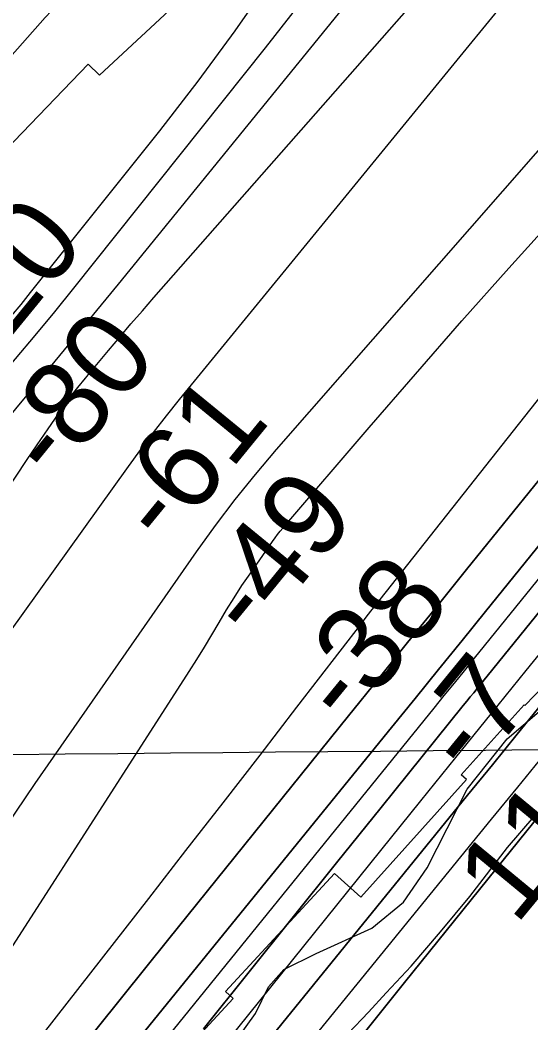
# Model space of a CAD drawing. Extents: x 3598634 to 3636690, y 517270 to 542944.
# Drawn here: x 3607463 to 3607864, y 528569 to 529355 of the extents above; entities that cross this region are included whole.
import ezdxf

# ---------------------------------------------------------------- set-up
doc = ezdxf.new("R2010")
doc.units = 0
for name, color, linetype in [('V-GRID-MAJR', 7, 'Continuous'), ('V-RIVR-EDGE', 7, 'Continuous'), ('V-RIVR-RANG', 7, 'Continuous'), ('V-RRAP-RVMT', 7, 'Continuous'), ('V-SITE-VEGE', 7, 'Continuous'), ('V-TOPO-DPTH', 7, 'Continuous'), ('V-TOPO-MAJR', 7, 'Continuous'), ('V-TOPO-MINR', 7, 'Continuous'), ('V-TOPO-WATR', 7, 'Continuous')]:
    doc.layers.add(name, color=color, linetype=linetype)

msp = doc.modelspace()

# ---------------------------------------------------------------- linework, layer by layer
at = {"layer": 'V-GRID-MAJR'}
msp.add_spline([(3602797.865, 528737.682), (3608075.829, 528784.895), (3613353.788, 528832.875), (3618631.739, 528881.623), (3623909.683, 528931.139), (3629187.62, 528981.4230000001), (3634465.549, 529032.474), (3634465.5500000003, 529032.474)], degree=3, dxfattribs=at)
at = {"layer": 'V-RIVR-EDGE'}
msp.add_lwpolyline([(3607634.578266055, 528557.2828526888), (3607647.8313884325, 528575.8602071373), (3607658.088833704, 528596.8462755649), (3607670.1294347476, 528610.6240151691), (3607695.3741721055, 528623.1684514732), (3607739.246734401, 528642.8707461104), (3607763.9104463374, 528663.220865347), (3607782.5872573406, 528690.1893814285), (3607813.9569472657, 528751.9454563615), (3607845.2717134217, 528791.489581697), (3607870.5387171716, 528813.0388624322), (3607896.9930070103, 528829.1822676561)], dxfattribs=at)
at = {"layer": 'V-RRAP-RVMT'}
for p, q in [((3607594.1901712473, 529376.2780618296), (3607525.4960925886, 529312.2596277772)), ((3607516.580398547, 529320.8680197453), (3607430.4427041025, 529231.6699390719)), ((3607525.4960925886, 529312.2596277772), (3607516.580398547, 529320.8680197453)), ((3607859.168962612, 528817.6532788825), (3607945.306657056, 528906.851359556)), ((3607809.3275471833, 528763.2942775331), (3607858.69286742, 528818.1145164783)), ((3607858.69286742, 528818.1145164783), (3607859.168962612, 528817.6532788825)), ((3607813.5323175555, 528759.4914313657), (3607809.3275471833, 528763.2942775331)), ((3607730.560063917, 528667.341525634), (3607813.5323175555, 528759.4914313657)), ((3607624.2160000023, 528593.327), (3607709.927226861, 528685.9194392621)), ((3607709.927226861, 528685.9194392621), (3607730.560063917, 528667.341525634)), ((3607529.4030000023, 528478.7670000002), (3607630.2730000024, 528587.7050000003)), ((3607630.2730000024, 528587.7050000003), (3607624.2160000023, 528593.327))]:
    msp.add_line(p, q, dxfattribs=at)
at = {"layer": 'V-SITE-VEGE'}
for points in [[(3607770.066, 528613.019), (3607793.127, 528640.116), (3607816.1890000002, 528667.909), (3607845.549, 528706.131), (3607866.5130000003, 528730.447)], [(3607720.468, 528560.229), (3607736.532, 528576.898), (3607750.506, 528592.18), (3607770.066, 528613.019)]]:
    msp.add_lwpolyline(points, dxfattribs=at)
at = {"layer": 'V-TOPO-DPTH'}
for points in [[(3607050.110421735, 527933.8661143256), (3607754.6678173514, 528800.4477853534), (3607773.1231306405, 528823.1621606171), (3607791.5686676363, 528845.8844668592), (3607809.999540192, 528868.6186695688), (3607828.420636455, 528891.360803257), (3608108.5226418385, 529237.3945285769), (3608193.270411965, 529341.3823736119), (3608278.475807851, 529444.99132357), (3608364.367642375, 529548.0319309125), (3608450.7171026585, 529650.6936431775), (3608605.4413867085, 529833.411271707), (3608614.8399220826, 529844.369931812), (3608624.329041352, 529855.2485710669), (3608633.9540364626, 529866.0071790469), (3608643.669615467, 529876.6857661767), (3609104.282173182, 530376.6107843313)], [(3609104.282173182, 530376.6107843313), (3608643.669615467, 529876.6857661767), (3608633.9540364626, 529866.0071790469), (3608624.329041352, 529855.2485710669), (3608614.8399220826, 529844.369931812), (3608605.4413867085, 529833.411271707), (3608450.7171026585, 529650.6936431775), (3608364.367642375, 529548.0319309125), (3608278.475807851, 529444.99132357), (3608193.270411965, 529341.3823736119), (3608108.5226418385, 529237.3945285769), (3607828.420636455, 528891.360803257), (3607809.999540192, 528868.6186695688), (3607791.5686676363, 528845.8844668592), (3607773.1231306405, 528823.1621606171), (3607754.6678173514, 528800.4477853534), (3607050.110421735, 527933.8661143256)], [(3608991.262616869, 530147.8676727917), (3608718.8075875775, 529843.8314700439), (3608702.0593536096, 529824.9491268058), (3608685.4407747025, 529805.9545085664), (3608669.0166783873, 529786.7914778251), (3608652.722237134, 529767.5161720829), (3608514.674114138, 529602.5153722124), (3608429.6663916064, 529500.4793089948), (3608344.943345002, 529398.2084138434), (3608260.647312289, 529295.5852707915), (3608176.635955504, 529192.7272958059), (3607892.148238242, 528842.9338263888), (3607872.700147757, 528819.0185201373), (3607853.2538833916, 528795.1017292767), (3607833.8103582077, 528771.182711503), (3607814.3686591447, 528747.262209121), (3607476.376953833, 528331.3583664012)], [(3607476.376953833, 528331.3583664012), (3607814.3686591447, 528747.262209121), (3607833.8103582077, 528771.182711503), (3607853.2538833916, 528795.1017292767), (3607872.700147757, 528819.0185201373), (3607892.148238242, 528842.9338263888), (3608176.635955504, 529192.7272958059), (3608260.647312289, 529295.5852707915), (3608344.943345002, 529398.2084138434), (3608429.6663916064, 529500.4793089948), (3608514.674114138, 529602.5153722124), (3608652.722237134, 529767.5161720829), (3608669.0166783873, 529786.7914778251), (3608685.4407747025, 529805.9545085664), (3608702.0593536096, 529824.9491268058), (3608718.8075875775, 529843.8314700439), (3608991.262616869, 530147.8676727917)], [(3607034.223612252, 527987.6309703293), (3607564.046678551, 528666.2927235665), (3607593.2248466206, 528703.7456360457), (3607622.3524560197, 528741.2377456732), (3607651.404227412, 528778.788651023), (3607680.405440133, 528816.378753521), (3607731.2039673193, 528882.3593449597), (3607734.7769871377, 528886.9815347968), (3607738.3619932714, 528891.5943715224), (3607741.9649788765, 528896.1931785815), (3607745.5799507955, 528900.7826325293), (3608274.0892009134, 529569.0736764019), (3608320.3402500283, 529626.5951807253), (3608367.2018034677, 529683.6065428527), (3608414.9791133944, 529739.8526916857), (3608463.3669276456, 529795.5886983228), (3608554.5295855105, 529898.8959307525)], [(3607034.223612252, 527987.6309703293), (3607564.046678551, 528666.2927235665), (3607593.2248466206, 528703.7456360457), (3607622.3524560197, 528741.2377456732), (3607651.404227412, 528778.788651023), (3607680.405440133, 528816.378753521), (3607731.2039673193, 528882.3593449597), (3607734.7769871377, 528886.9815347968), (3607738.3619932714, 528891.5943715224), (3607741.9649788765, 528896.1931785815), (3607745.5799507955, 528900.7826325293), (3608274.0892009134, 529569.0736764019), (3608320.3402500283, 529626.5951807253), (3608367.2018034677, 529683.6065428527), (3608414.9791133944, 529739.8526916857), (3608463.3669276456, 529795.5886983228), (3608554.5295855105, 529898.8959307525)], [(3607486.2819548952, 528518.1246214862), (3607579.8394687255, 528634.4834955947), (3607720.9145705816, 528809.5522122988), (3607744.066510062, 528838.2711207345), (3607767.226098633, 528866.9838569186), (3607790.397160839, 528895.6873347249), (3607813.5758721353, 528924.3846402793), (3607874.8316391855, 529000.1937296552), (3607928.7530441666, 529066.7018234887), (3607982.8198766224, 529133.0910840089), (3608037.1048502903, 529199.302094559), (3608091.535251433, 529265.3942717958), (3608556.611860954, 529828.2246806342), (3608577.032808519, 529852.5722801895), (3608597.6881704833, 529876.7163432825), (3608618.6951540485, 529900.5551016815)], [(3608618.6951540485, 529900.5551016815), (3608597.6881704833, 529876.7163432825), (3608577.032808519, 529852.5722801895), (3608556.611860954, 529828.2246806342), (3608091.535251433, 529265.3942717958), (3608037.1048502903, 529199.302094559), (3607982.8198766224, 529133.0910840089), (3607928.7530441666, 529066.7018234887), (3607874.8316391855, 529000.1937296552), (3607813.5758721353, 528924.3846402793), (3607790.397160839, 528895.6873347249), (3607767.226098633, 528866.9838569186), (3607744.066510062, 528838.2711207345), (3607720.9145705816, 528809.5522122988), (3607579.8394687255, 528634.4834955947), (3607486.2819548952, 528518.1246214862)], [(3608692.0499146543, 529894.310394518), (3608646.0571142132, 529844.3928552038), (3608644.3113008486, 529842.4744016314), (3608642.5815031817, 529840.5417904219), (3608640.875729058, 529838.5879427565), (3608639.1859706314, 529836.6199374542), (3608610.975637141, 529803.3503869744), (3608595.2558213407, 529784.6846881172), (3608579.620121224, 529765.9492680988), (3608564.110594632, 529747.1092663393), (3608548.685183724, 529728.1995434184), (3607821.8677533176, 528831.0740898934), (3607819.144475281, 528827.7105861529), (3607816.4225722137, 528824.3459707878), (3607813.7027316, 528820.9796879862), (3607810.984265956, 528817.61229356), (3607746.463470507, 528737.6395229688), (3607711.520787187, 528694.2567081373), (3607676.6249686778, 528650.8362916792), (3607641.799447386, 528607.3594727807), (3607607.020790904, 528563.8450522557)], [(3607607.020790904, 528563.8450522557), (3607641.799447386, 528607.3594727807), (3607676.6249686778, 528650.8362916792), (3607711.520787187, 528694.2567081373), (3607746.463470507, 528737.6395229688), (3607810.984265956, 528817.61229356), (3607813.7027316, 528820.9796879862), (3607816.4225722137, 528824.3459707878), (3607819.144475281, 528827.7105861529), (3607821.8677533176, 528831.0740898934), (3608548.685183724, 529728.1995434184), (3608564.110594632, 529747.1092663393), (3608579.620121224, 529765.9492680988), (3608595.2558213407, 529784.6846881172), (3608610.975637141, 529803.3503869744), (3608639.1859706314, 529836.6199374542), (3608640.875729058, 529838.5879427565), (3608642.5815031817, 529840.5417904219), (3608644.3113008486, 529842.4744016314), (3608646.0571142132, 529844.3928552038), (3608692.0499146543, 529894.310394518)], [(3608826.278553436, 529889.7496636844), (3608805.0948457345, 529867.4214339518), (3608784.247844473, 529844.7785133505), (3608763.6253141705, 529821.9257988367), (3608724.162120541, 529777.5310744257), (3608723.444853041, 529776.7138432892), (3608722.7345501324, 529775.8906787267), (3608721.3418026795, 529774.2206158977), (3607992.342167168, 528881.1336073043), (3607976.182451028, 528861.3303280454), (3607960.0268139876, 528841.5237226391), (3607943.8772955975, 528821.7121280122), (3607927.731856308, 528801.8972072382), (3607900.6113318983, 528768.6023214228), (3607898.0316686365, 528765.4303601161), (3607895.455278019, 528762.2557470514), (3607892.88379637, 528759.0771563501), (3607890.315587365, 528755.8959138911), (3607830.1698473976, 528681.2754461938), (3607797.532199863, 528640.781193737), (3607764.895854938, 528600.2858915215), (3607732.261463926, 528559.7890146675)]]:
    msp.add_lwpolyline(points, dxfattribs=at)
at = {"layer": 'V-TOPO-MAJR'}
for points in [[(3606938.5062461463, 528528.361308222), (3607012.804781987, 528597.746612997), (3607085.3402082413, 528668.8656599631), (3607155.2309701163, 528742.5853202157), (3607223.3586224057, 528818.0387226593), (3607443.875212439, 529071.4225473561), (3607459.518815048, 529089.6314336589), (3607475.005335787, 529107.9712529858), (3607490.256233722, 529126.507471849), (3607505.3500497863, 529145.1746237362), (3607655.732426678, 529333.6088707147), (3607744.7138808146, 529447.4732628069), (3607832.115936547, 529562.5123585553), (3607917.1488946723, 529679.3135097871), (3608000.6024543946, 529797.2893646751), (3608165.5331937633, 530035.5755289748)], [(3607396.4622327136, 528534.538567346), (3607595.724040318, 528844.2248021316), (3607601.7802237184, 528853.7867448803), (3607607.7442807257, 528863.4049053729), (3607613.57014814, 528873.1073924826), (3607619.3038891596, 528882.8660973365), (3607625.089083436, 528892.590358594), (3607631.034815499, 528902.2126010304), (3607637.221354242, 528911.6818152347), (3607643.568430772, 528921.0490106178), (3607661.255984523, 528946.4565765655), (3607663.1754045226, 528949.1261234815), (3607665.147564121, 528951.7548337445), (3607667.1988331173, 528954.3222890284), (3607669.3028417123, 528956.8489076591), (3607737.1862056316, 529035.8879061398), (3607773.4384315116, 529077.7560607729), (3607809.9131516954, 529119.4278847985), (3607846.721613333, 529160.8052129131), (3607883.752569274, 529201.9862104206), (3608512.639176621, 529895.7241702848)]]:
    msp.add_lwpolyline(points, dxfattribs=at)
at = {"layer": 'V-TOPO-MINR'}
for points in [[(3607269.9346052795, 528037.4466619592), (3607833.1789492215, 528728.441475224), (3607853.695733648, 528753.6155649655), (3607874.209999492, 528778.7917066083), (3607894.720487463, 528803.9709261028), (3607915.2284568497, 528829.1521974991), (3608012.971921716, 528949.1875763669), (3608082.5213329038, 529034.2464083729), (3608152.2995331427, 529119.1163572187), (3608222.420916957, 529203.7029813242), (3608292.771089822, 529288.1007222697), (3608697.7320062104, 529771.9288514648), (3608703.7902030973, 529779.1057189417), (3608709.8880741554, 529786.2484280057), (3608716.04545647, 529793.3398994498), (3608722.2425129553, 529800.3972124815), (3609349.791717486, 530509.062902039)], [(3607050.110421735, 527933.8661143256), (3607754.6678173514, 528800.4477853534), (3607773.1231306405, 528823.1621606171), (3607791.5686676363, 528845.8844668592), (3607809.999540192, 528868.6186695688), (3607828.420636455, 528891.360803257), (3608108.5226418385, 529237.3945285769), (3608193.270411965, 529341.3823736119), (3608278.475807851, 529444.99132357), (3608364.367642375, 529548.0319309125), (3608450.7171026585, 529650.6936431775), (3608605.4413867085, 529833.411271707), (3608614.8399220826, 529844.369931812), (3608624.329041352, 529855.2485710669), (3608633.9540364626, 529866.0071790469), (3608643.669615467, 529876.6857661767), (3609104.282173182, 530376.6107843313)], [(3607153.579419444, 528530.0961648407), (3607214.1284992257, 528623.3245871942), (3607451.633225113, 528985.0946669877), (3607459.8764041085, 528997.5484505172), (3607468.1816531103, 529009.9603620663), (3607476.58000712, 529022.3094656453), (3607485.0404311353, 529034.616697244), (3607496.207898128, 529050.7316771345), (3607499.1759406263, 529054.9164984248), (3607502.2036420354, 529059.0566857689), (3607505.32083181, 529063.1299221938), (3607508.497680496, 529067.1585246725), (3607514.438003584, 529074.5249937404), (3607514.690223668, 529074.8362432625), (3607515.4537861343, 529075.7643346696), (3607532.4574206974, 529096.1767786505), (3607541.2583585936, 529106.6542355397), (3607550.1162340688, 529117.0829268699), (3607559.059515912, 529127.438469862), (3607568.059735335, 529137.7452472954), (3608344.7420183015, 530019.8355773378)], [(3607538.861497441, 528507.8470592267), (3607788.102173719, 528815.6048933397), (3607796.0217690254, 528825.383855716), (3607803.941370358, 528835.1628132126), (3607811.8609807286, 528844.9417633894), (3607819.7805971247, 528854.7207086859), (3608327.2406076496, 529481.3191128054), (3608377.5500924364, 529543.0180431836), (3608428.1322050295, 529604.4911170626), (3608479.123259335, 529665.6254061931), (3608530.386941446, 529726.5338388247), (3608622.313038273, 529835.0183809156), (3608627.857922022, 529841.4799990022), (3608633.4557975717, 529847.8947890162), (3608639.1331608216, 529854.2393369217), (3608644.863515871, 529860.5370567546), (3608795.867747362, 530024.4293374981)], [(3607315.303971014, 528512.7430944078), (3607366.934778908, 528595.0148138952), (3607420.365062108, 528676.1294302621), (3607474.994995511, 528756.4726445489), (3607601.505611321, 528938.1919034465), (3607616.4214247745, 528958.8716412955), (3607631.783973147, 528979.2019377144), (3607647.8166238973, 528999.0080719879), (3607664.2960095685, 529018.4647648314), (3608476.761360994, 529945.8585601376)], [(3608167.609300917, 529919.3445388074), (3608117.7852957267, 529858.0963726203), (3608067.950229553, 529796.8572059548), (3608018.10778939, 529735.62403897), (3607539.9595716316, 529148.3106995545), (3607517.056991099, 529120.2706469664), (3607494.0950201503, 529092.2794725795), (3607471.0439635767, 529064.3616154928), (3607447.9335165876, 529036.4926366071), (3606763.4822901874, 528213.7816602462), (3606757.299481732, 528206.281166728), (3606751.1622999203, 528198.743864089), (3606745.0935580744, 528191.1513477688), (3606739.070442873, 528183.5220223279), (3606733.287483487, 528175.730280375), (3606727.7774810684, 528167.7598566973), (3606722.6769141, 528159.5214104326), (3606717.8493040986, 528151.1042824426), (3606633.923438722, 527995.8083232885), (3606585.2959337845, 527910.9416458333), (3606533.960073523, 527827.8424987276), (3606478.5616802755, 527747.3946471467), (3606420.4549317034, 527668.7143259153), (3606248.639550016, 527447.7750288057)], [(3607034.223612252, 527987.6309703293), (3607564.046678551, 528666.2927235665), (3607593.2248466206, 528703.7456360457), (3607622.3524560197, 528741.2377456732), (3607651.404227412, 528778.788651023), (3607680.405440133, 528816.378753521), (3607731.2039673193, 528882.3593449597), (3607734.7769871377, 528886.9815347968), (3607738.3619932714, 528891.5943715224), (3607741.9649788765, 528896.1931785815), (3607745.5799507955, 528900.7826325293), (3608274.0892009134, 529569.0736764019), (3608320.3402500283, 529626.5951807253), (3608367.2018034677, 529683.6065428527), (3608414.9791133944, 529739.8526916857), (3608463.3669276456, 529795.5886983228), (3608554.5295855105, 529898.8959307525)], [(3607230.391889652, 528518.152562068), (3607261.079917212, 528571.3685838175), (3607291.875722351, 528624.5226713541), (3607297.412073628, 528634.04516238), (3607331.865051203, 528691.3908644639), (3607367.3935200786, 528748.0403263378), (3607404.5352259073, 528803.6454278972), (3607442.7524230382, 528858.554289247), (3607548.0453323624, 529005.2903303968), (3607557.7997309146, 529018.6145053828), (3607567.720346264, 529031.8112339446), (3607577.890286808, 529044.816792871), (3607588.2264441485, 529057.6949053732), (3608053.775307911, 529626.5599169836), (3608110.773650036, 529695.4553882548), (3608168.256237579, 529763.9399911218), (3608226.4651932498, 529831.8082913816), (3608285.1583943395, 529899.2657232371)], [(3607486.2819548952, 528518.1246214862), (3607579.8394687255, 528634.4834955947), (3607720.9145705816, 528809.5522122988), (3607744.066510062, 528838.2711207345), (3607767.226098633, 528866.9838569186), (3607790.397160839, 528895.6873347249), (3607813.5758721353, 528924.3846402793), (3607874.8316391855, 529000.1937296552), (3607928.7530441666, 529066.7018234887), (3607982.8198766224, 529133.0910840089), (3608037.1048502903, 529199.302094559), (3608091.535251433, 529265.3942717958), (3608556.611860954, 529828.2246806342), (3608577.032808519, 529852.5722801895), (3608597.6881704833, 529876.7163432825), (3608618.6951540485, 529900.5551016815)], [(3607607.020790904, 528563.8450522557), (3607641.799447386, 528607.3594727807), (3607676.6249686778, 528650.8362916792), (3607711.520787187, 528694.2567081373), (3607746.463470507, 528737.6395229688), (3607810.984265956, 528817.61229356), (3607813.7027316, 528820.9796879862), (3607816.4225722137, 528824.3459707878), (3607819.144475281, 528827.7105861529), (3607821.8677533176, 528831.0740898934), (3608548.685183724, 529728.1995434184), (3608564.110594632, 529747.1092663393), (3608579.620121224, 529765.9492680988), (3608595.2558213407, 529784.6846881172), (3608610.975637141, 529803.3503869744), (3608639.1859706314, 529836.6199374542), (3608640.875729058, 529838.5879427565), (3608642.5815031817, 529840.5417904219), (3608644.3113008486, 529842.4744016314), (3608646.0571142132, 529844.3928552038), (3608692.0499146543, 529894.310394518)], [(3607616.821328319, 528543.0276400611), (3607659.8796647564, 528596.736166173), (3607703.0201507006, 528650.3787293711), (3607746.2154029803, 528703.9773172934), (3607777.6016978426, 528742.8618854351), (3607805.1597452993, 528776.9731712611), (3607832.737616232, 528811.0684085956), (3607860.345222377, 528845.1395731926), (3607887.9726519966, 528879.1946892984), (3608477.194766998, 529604.8556301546), (3608507.459859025, 529641.9636581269), (3608537.8320823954, 529678.9834015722), (3608568.365002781, 529715.8707182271), (3608599.0050545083, 529752.6697503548), (3608607.7246853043, 529763.0959346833), (3608634.275550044, 529794.4497895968), (3608661.080028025, 529825.5825634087), (3608688.2649258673, 529856.3837155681), (3608715.70343695, 529886.9637866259)], [(3607732.261463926, 528559.7890146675), (3607764.895854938, 528600.2858915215), (3607797.532199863, 528640.781193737), (3607830.1698473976, 528681.2754461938), (3607890.315587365, 528755.8959138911), (3607892.88379637, 528759.0771563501), (3607895.455278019, 528762.2557470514), (3607898.0316686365, 528765.4303601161), (3607900.6113318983, 528768.6023214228), (3607927.731856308, 528801.8972072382), (3607943.8772955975, 528821.7121280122), (3607960.0268139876, 528841.5237226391), (3607976.182451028, 528861.3303280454), (3607992.342167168, 528881.1336073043), (3608721.3418026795, 529774.2206158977), (3608722.7345501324, 529775.8906787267), (3608723.444853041, 529776.7138432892), (3608724.162120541, 529777.5310744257), (3608763.6253141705, 529821.9257988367), (3608784.247844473, 529844.7785133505), (3608805.0948457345, 529867.4214339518), (3608826.278553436, 529889.7496636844)], [(3607456.3638915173, 529123.2878979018), (3607463.8693567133, 529132.4101502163), (3607471.297528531, 529141.5968292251), (3607572.7249611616, 529268.6879057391), (3607602.7640332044, 529307.5670514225), (3607631.965568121, 529347.0455572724), (3607659.9107973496, 529387.4231033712), (3607687.018489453, 529428.4000096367), (3607714.1829125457, 529470.9012853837), (3607716.5403348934, 529484.6297785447), (3607714.4250917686, 529495.6215157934), (3607705.600850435, 529502.5081191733), (3607692.30394363, 529506.6579666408), (3607669.2681935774, 529502.3783242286), (3607647.2276236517, 529495.6329972), (3607626.6798239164, 529485.1891432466), (3607607.127204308, 529472.2796046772), (3607587.809408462, 529456.9404281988), (3607560.0526528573, 529433.688559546), (3607533.163893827, 529409.520417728), (3607507.577129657, 529383.9778661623), (3607482.858362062, 529357.519041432), (3607359.6905202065, 529218.5517738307)]]:
    msp.add_lwpolyline(points, dxfattribs=at)
at = {"layer": 'V-TOPO-WATR'}
msp.add_lwpolyline([(3607476.376953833, 528331.3583664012), (3607814.3686591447, 528747.262209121), (3607833.8103582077, 528771.182711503), (3607853.2538833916, 528795.1017292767), (3607872.700147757, 528819.0185201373), (3607892.148238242, 528842.9338263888), (3608176.635955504, 529192.7272958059), (3608260.647312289, 529295.5852707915), (3608344.943345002, 529398.2084138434), (3608429.6663916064, 529500.4793089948), (3608514.674114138, 529602.5153722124), (3608652.722237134, 529767.5161720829), (3608669.0166783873, 529786.7914778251), (3608685.4407747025, 529805.9545085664), (3608702.0593536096, 529824.9491268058), (3608718.8075875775, 529843.8314700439), (3608991.262616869, 530147.8676727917)], dxfattribs=at)

# ---------------------------------------------------------------- texts
at = {"layer": 'V-RIVR-RANG'}
for s, height, rotation, p in [('-120', 67.00000000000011, 50.73541666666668, (3607402.4644791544, 529041.3599864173)), ('-80', 67.00000000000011, 50.73541666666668, (3607490.748961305, 528991.3569314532)), ('-61', 67.00000000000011, 50.73541666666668, (3607578.0317632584, 528940.1295178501)), ('-49', 67.00000000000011, 50.73541666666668, (3607646.6175348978, 528866.0277429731)), ('-38', 67.00000000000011, 50.73541666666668, (3607721.0454410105, 528799.0748934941)), ('-7', 67.00000000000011, 50.73541666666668, (3607817.6782581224, 528759.2831605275)), ('11.5', 67, 50.44832571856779, (3607852.1406342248, 528644.3807617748))]:
    msp.add_text(s, height=height, rotation=rotation, dxfattribs=at).set_placement(p)

doc.saveas('drawing.dxf')
